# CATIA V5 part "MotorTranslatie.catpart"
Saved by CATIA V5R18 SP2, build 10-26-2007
Part number: 8156181_EMMT_ST_57_L_RM____400_.catpart
Property "ARTICLENO": "8156181 EMMT-ST-57-L-RM---(400)"
Property "B1": "56.400"
Property "B2": "47.140"
Property "BOMINFO": "8156181 EMMT-ST-57-L-RM"
Property "CATALOG": "Festo"
Property "CNSMASSEXACT": "1.260"
Property "CREATOR": "CADENAS GmbH"
Property "D1": "6.350"
Property "D2": "38.100"
Property "D3": "M17"
Property "D4": "5"
Property "GTIN": "4052568639693"
Property "H1": "88.000"
Property "H3": "49.300"
Property "L": "131.100"
Property "L1": "110.500"
Property "L2": "20.600"
Property "L3": "1.600"
Property "L4": "5.000"
Property "L5": "16.700"
Property "L6": "33.400"
Property "L7": "11.000"
Property "LINA": "8156181 EMMT-ST-57-L-RM"
Property "LOG": "High"
Property "NB": "8156181 EMMT-ST-57-L-RM---(400)"
Property "NBSYN": "$TNR. $TYP.---($LOG.)"
Property "NN": "EMMT-ST"
Property "NT": "stepper motor"
Property "R": "3.000"
Property "SUPPLIER": "FESTO"
Property "TNR": "8156181"
Property "TYP": "EMMT-ST-57-L-RM"
Bounding box of the stored display mesh (mm): x -28.2 to 28.2, y -28.2 to 59.8, z -110.5 to 20.6
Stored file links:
  C:\Users\MIRCEA\Desktop\PRRO\CATIAV5\MotorTranslatie.catpart
  C:\Program Files (x86)\Dassault Systemes\B21\intel_a\startup\materials\French\Catalog.CATMaterial
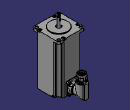
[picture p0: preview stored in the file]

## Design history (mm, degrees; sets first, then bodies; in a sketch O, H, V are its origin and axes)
Set1
  Plane1: type Offset, RefPlane zx-plane, Offset 3.5
Body1 "8156181_EMMT_ST_57_L_RM____400_.catpart" (main body)
  Solid1: solid without history
  Sketch1 on Plane1, origin (0, 3.5, 0), H (-1, 0, 0), V (0, 0, 1)
    construction line L1 (0, 18.5) -> (0, 13.5)
    line L2 (1.25, 18.5) -> (1.25, 13.5)
    line L3 (-1.25, 13.5) -> (-1.25, 18.5)
    arc A1 centre (0, 13.5) radius 1.25 from (1.25, 13.5) to (-1.25, 13.5) cw
    arc A2 centre (0, 18.5) radius 1.25 from (-1.25, 18.5) to (1.25, 18.5) cw
    length L1 = 5
    distance L1 L2 = 1.25
    vertical: L1 V
    tangency: A1 L2, A2 L2, A1 L3, A2 L3
  Pocket1: profile Sketch1, direction (0, -1, 0), length 2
